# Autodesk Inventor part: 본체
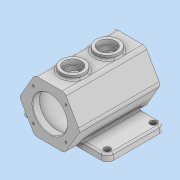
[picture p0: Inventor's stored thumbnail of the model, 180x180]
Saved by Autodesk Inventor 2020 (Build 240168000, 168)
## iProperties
Created: 2021-06
Part Number: 본체
Material: 일반
Document SubType Name: Modeling
Designer: MIRAE
Density: 1 g/cm^3
Appearance: 기본값
Mass: 553.742 g
Surface Area: 1103.82 cm^2
Volume: 553.742 cm^3
Author: MIRAE
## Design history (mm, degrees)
sketch "스케치1"
  geometry: L1 (-75, 12)-(75, 12); L2 (75, 12)-(75, 0); L3 (75, 0)-(-75, 0); L4 (-75, 0)-(-75, 12); 2 further points
  constraints: 8 end point, 2 parallel, 1 coincident, 1 horizontal, 1 midpoint, 1 perpendicular
  dimensions: "d0" = 150 distance of L1.start L1.end; "d1" = 12 distance of L1.end L2.end
extrude "돌출1" new body sketch "스케치1" stored distance "d2" = 100; taper "d3" = 0 deg
sketch "스케치2"
  geometry: L1 (52.5, 50)-(26.25, 4.534); L2 (26.25, 4.534)-(-26.25, 4.534); L3 (-26.25, 4.534)-(-52.5, 50); L4 (-52.5, 50)-(-26.25, 95.466); L5 (-26.25, 95.466)-(26.25, 95.466); L6 (26.25, 95.466)-(52.5, 50); A1 r 52.5 centre (0, 50) between (0, 102.5) and (52.5, 50); 3 further points
  constraints: 12 end point, 2 coincident, 2 point on circle, 1 centre point, 13 other
  dimensions: "d4" = 105 diameter of A1; "d5" = 50 distance of point (0, 0) A1.centre
extrude "돌출2" join sketch "스케치2" distance "d6" = 75; taper "d7" = 0 deg
sketch "스케치3" dims "d8" = 105
  geometry: L1 (-52.5, 50)-(-26.25, 95.466); L2 (-26.25, 95.466)-(26.25, 95.466); L3 (26.25, 95.466)-(52.5, 50); L4 (52.5, 50)-(26.25, 4.534); L5 (26.25, 4.534)-(-26.25, 4.534); L6 (-26.25, 4.534)-(-52.5, 50); 3 further points
  constraints: 12 end point, 1 coincident, 1 horizontal alignment, 15 other
  dimensions: "d9" = 50 distance of point (0, 0) point (0, 50)
extrude "돌출3" join sketch "스케치3" distance "d10" = 65; taper "d11" = 0 deg
sketch "스케치4"
  geometry: L1 (102.5, 35)-(77.5, 35); L2 (77.5, 35)-(77.5, 55); L3 (77.5, 55)-(102.5, 55); L4 (102.5, 55)-(102.5, 35); L5 (95.466, 75)-(50, 75) reference; L6 (95.466, -65)-(95.466, 75) reference; L7 (50, 75)-(50, -65); 1 further point
  constraints: 10 end point, 2 parallel, 1 horizontal, 1 perpendicular, 1 vertical
  dimensions: "d13" = 40 distance between parallel lines of L5 L1; "d15" = 40 diameter of L3 L1; "d18" = 25 distance between parallel lines of L2 L4; "d46" = 52.5 distance between parallel lines of L7 L4
revolve "회전1" sketch "스케치4" stored, may be unused: angle "d19" = 90 deg
sketch "스케치5"
  geometry: L1 (102.5, -5)-(77.5, -5); L2 (77.5, -5)-(77.5, -25); L3 (77.5, -25)-(102.5, -25); L4 (102.5, -25)-(102.5, -5); L5 (95.466, -65)-(95.466, 75) reference; L6 (95.466, 75)-(50, 75) reference; L7 (50, 75)-(50, -86.635); 1 further point
  constraints: 10 end point, 2 parallel, 1 horizontal, 1 perpendicular, 1 vertical
  dimensions: "d20" = 40 diameter of L1 L3; "d22" = 100 distance between parallel lines of L3 L6; "d23" = 25 distance of L1.start L1.end; "d47" = 52.5 distance between parallel lines of L7 L4
revolve "회전2" sketch "스케치5" stored, may be unused: angle "d24" = 90 deg
sketch "스케치6"
  geometry: L1 (50, 75)-(50, -65); L2 (95.466, 75)-(50, 75) reference; L3 (50, -65)-(95.466, -65) reference; L4 (50, 75)-(80, 75); L5 (80, 75)-(80, 63); L6 (80, 63)-(87.5, 63); L7 (87.5, 63)-(87.5, -53); L8 (87.5, -53)-(80, -53); L9 (80, -53)-(80, -65); L10 (80, -65)-(50, -65); 1 further point
  constraints: 16 end point, 5 perpendicular, 4 point on line, 1 collinear, 1 vertical
  dimensions: "d25" = 50 horizontal distance of L1.start point (0, 0); "d26" = 12 distance of L4.end L5.end; "d27" = 12 distance of L8.end L9.end; "d28" = 60 diameter of L5 L1; "d29" = 75 diameter of L7 L1; "d30" = 60 diameter of L9 L1
revolve "회전3" sketch "스케치6" stored, may be unused: angle "d31" = 90 deg
sketch "스케치7"
  geometry: C1 r 20 at (0, 0) reference; 2 further points
  constraints: 1 coincident
hole "구멍1" sketch "스케치7" at (0, 0) diameter "d32" = 25; stored, may be unused: countersink angle "d36" = 90 deg, drill point angle "d38" = 118 deg; dims "d33" = 6, "d34" = 30, "d35" = 8, "d37" = 8
sketch "스케치8"
  geometry: C1 r 20 at (0, 0) reference; 2 further points
  constraints: 1 coincident
hole "구멍2" sketch "스케치8" at (0, 0) diameter "d39" = 25; stored, may be unused: countersink angle "d43" = 90 deg, drill point angle "d45" = 118 deg; dims "d40" = 6, "d41" = 30, "d42" = 8, "d44" = 8
fillet "모깎기1" dims "d48" = 5
fillet "모깎기2" dims "d49" = 10
sketch "스케치9"
  geometry: L1 (0, 50)-(28.284, 78.284); L2 (0, 50)-(0, 90); C1 r 30 at (0, 50) reference; A1 r 40 centre (0, 50) between (28.284, 78.284) and (0, 90); 2 further points
  constraints: 4 end point, 2 coincident, 2 point on circle, 1 centre point, 1 vertical
  dimensions: "d50" = 80 diameter of A1; "d51" = 45 deg angle of L2 L1
hole "구멍3" sketch "스케치9" at (28.284, 78.284) diameter "d52" = 3.45873; stored, may be unused: countersink angle "d56" = 90 deg, drill point angle "d58" = 118 deg; dims "d53" = 8, "d54" = 30, "d55" = 8, "d57" = 10
sketch "스케치10" dims "d62" = 80
  geometry: L1 (0, 50)-(0, 90); C1 r 30 at (0, 50) reference; 2 further points
  constraints: 2 coincident, 2 end point, 1 vertical alignment, 2 other
hole "구멍4" sketch "스케치10" at (0, 90) diameter "d63" = 3.45873; stored, may be unused: countersink angle "d67" = 90 deg, drill point angle "d69" = 118 deg; dims "d64" = 8, "d65" = 30, "d66" = 8, "d68" = 10
sketch "스케치11"
  geometry: A1 r 10 centre (-95.561, 10) between (-105.561, 10) and (-95.561, 0) reference; A2 r 10 centre (-95.561, 90) between (-95.561, 100) and (-105.561, 90) reference; A3 r 10 centre (34.439, 90) between (44.439, 90) and (34.439, 100) reference; A4 r 10 centre (34.439, 10) between (34.439, 0) and (44.439, 10) reference; 5 further points
  constraints: 4 coincident
hole "구멍5" sketch "스케치11" at (-95.561, 10), (-95.561, 90), (34.439, 90), (34.439, 10) diameter "d73" = 11; stored, may be unused: countersink angle "d77" = 90 deg, drill point angle "d79" = 118 deg; dims "d74" = 8, "d75" = 30, "d76" = 8, "d78" = 10
fillet "모깎기6" dims "d92" = 8
fillet "모깎기3" dims "d80" = 3
fillet "모깎기4" dims "d81" = 3
fillet "모깎기5" dims "d82" = 3
chamfer "모따기1" distance "d83" = 1; stored, may be unused: second distance "d84" = 2, angle "d85" = 45 deg
sketch "스케치12"
  geometry: L1 (21, 65)-(21, 15); L2 (21, 15)-(1, 15); L3 (1, 15)-(1, 65); L4 (1, 65)-(21, 65); L5 (21, 65)-(1, 15); L6 (7, -10)-(39.707, -10) reference; L7 (-3, 80)-(-3, 0) reference; 2 further points
  constraints: 2 end point, 1 midpoint, 1 vertical, 2 other
  dimensions: "d86" = 50 distance of L2.end L3.end; "d87" = 20 distance of L1.end L2.end; "d88" = 50 distance from line of L6 point (11, 40); "d89" = 14 distance from line of L7 point (11, 40)
feature "엠보싱1" sketch "스케치12" dims "d0" = 150, "d1" = 12, "d90" = 0.5, "d91" = 0
node "솔리드1"
pattern_circular "원형 패턴1" dims angle "d60" = 360 deg
pattern_circular "원형 패턴2" dims angle "d71" = 360 deg
feature "A9D066F2-1C7D-4E18-AEED-F7BC21143FA4" dims "d73" = 11, "d74" = 8, "d75" = 30, "d76" = 8, "d77" = 90 deg, "d78" = 10, "d79" = 118 deg
